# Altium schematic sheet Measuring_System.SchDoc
size A3
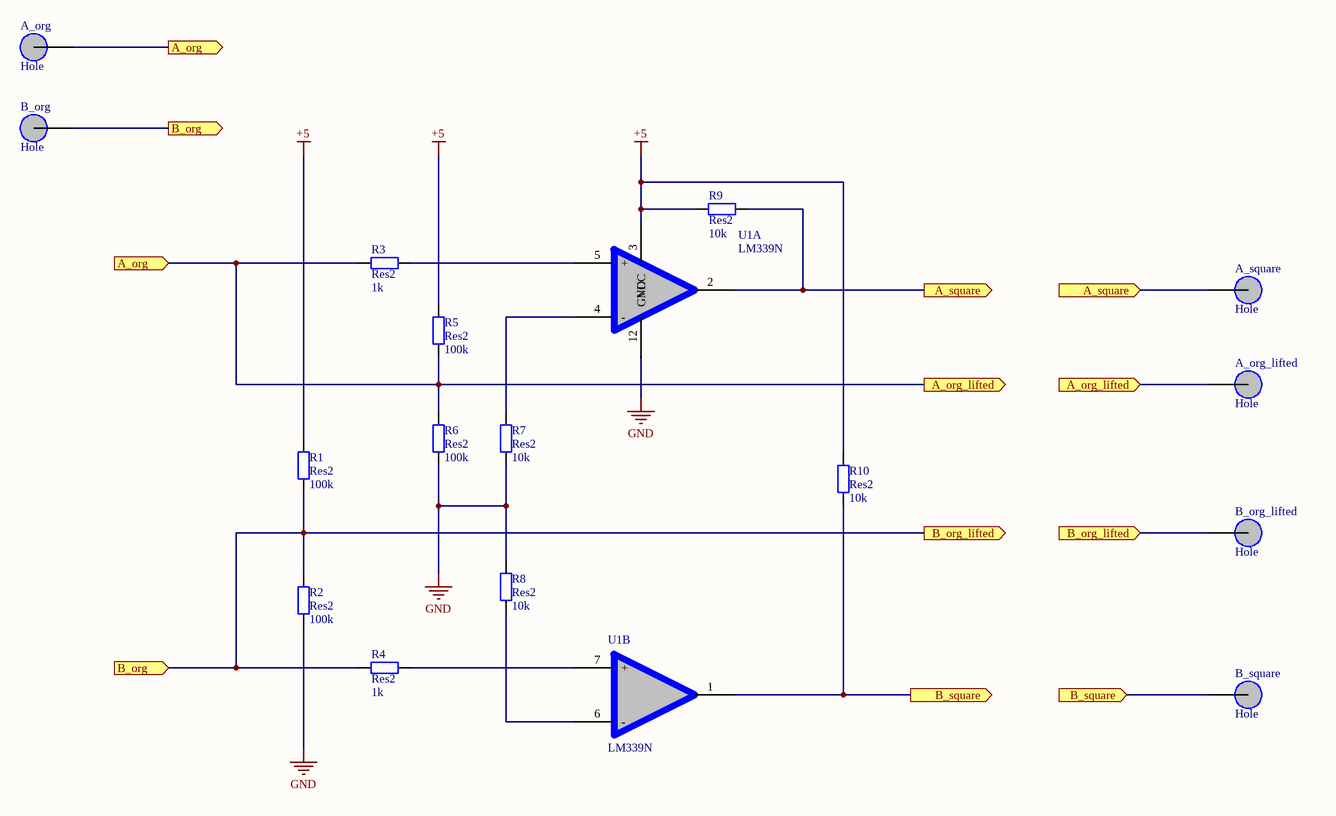
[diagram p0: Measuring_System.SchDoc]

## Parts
A_org  Hole  [Hole]
A_org_lifted  Hole  [Hole]
A_square  Hole  [Hole]
B_org  Hole  [Hole]
B_org_lifted  Hole  [Hole]
B_square  Hole  [Hole]
R1  Res2  value 100k  [AXIAL-0.4]
R2  Res2  value 100k  [AXIAL-0.4]
R3  Res2  value 1k  [AXIAL-0.4]
R4  Res2  value 1k  [AXIAL-0.4]
R5  Res2  value 100k  [AXIAL-0.4]
R6  Res2  value 100k  [AXIAL-0.4]
R7  Res2  value 10k  [AXIAL-0.4]
R8  Res2  value 10k  [AXIAL-0.4]
R9  Res2  value 10k  [AXIAL-0.4]
R10  Res2  value 10k  [AXIAL-0.4]
U1  LM339N  [LM339N]  (parts A,B of 4)

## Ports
A_org (in), A_org (out), A_org_lifted (in), A_org_lifted (out), A_square (in), A_square (out), B_org (in), B_org (out), B_org_lifted (in), B_org_lifted (out), B_square (in), B_square (out)

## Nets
+5: R1.2 R5.2 R9.1 R10.2 U1.3(VCC)
GND: R2.1 R6.1 R7.1 R8.2 U1.12(GND)
A_org: A_org.1(~PR) A_org_lifted.1(~PR) R3.2 R5.1 R6.2 ; port A_org, port A_org_lifted
A_square: A_square.1(~PR) R9.2 U1.2(1OUT) ; port A_square
B_org: B_org.1(~PR) B_org_lifted.1(~PR) R1.1 R2.2 R4.2 ; port B_org, port B_org_lifted
B_square: B_square.1(~PR) R10.1 U1.1(2OUT) ; port B_square
NetR3_1: R3.1 U1.5(+)
NetR4_1: R4.1 U1.7(+)
NetR7_2: R7.2 U1.4(-)
NetR8_1: R8.1 U1.6(-)

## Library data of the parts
R1-R10 = Res2: Resistor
